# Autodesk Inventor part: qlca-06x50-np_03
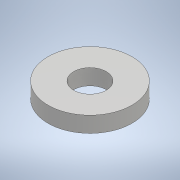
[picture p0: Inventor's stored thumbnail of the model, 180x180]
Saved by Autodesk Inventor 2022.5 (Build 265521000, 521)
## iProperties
Part Number: qlca-06x50-np_03
Material: 一般
Document SubType Name: Modeling
Designer: ImaoCorp
Density: 1 g/cm^3
Appearance: 既定
Author: ImaoCorp
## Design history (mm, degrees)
feature "qlca-06x50-np_03"
node "ソリッド1"
